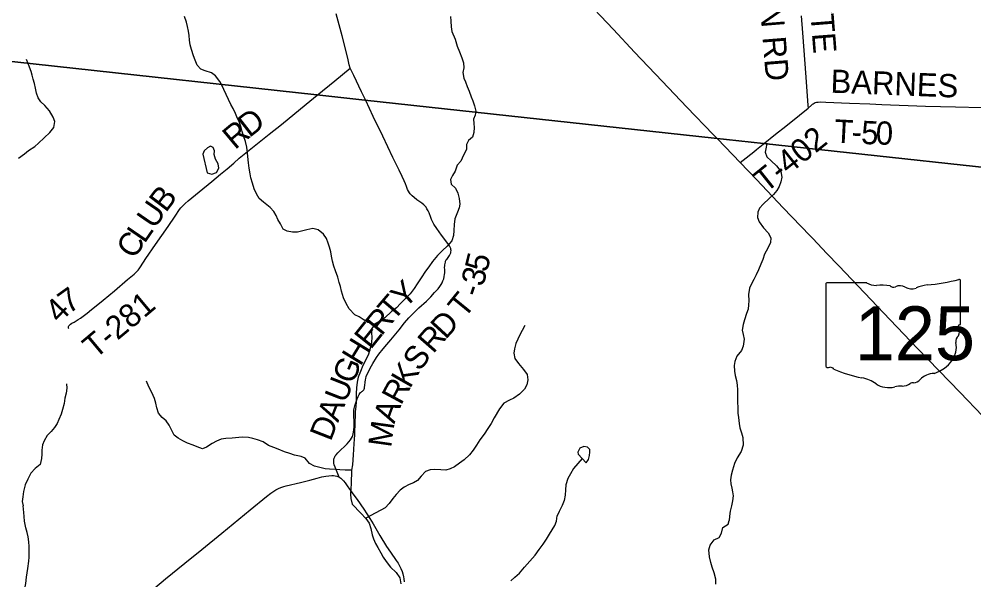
# Model space of a CAD drawing. Extents: x 1451455 to 1749751, y 218250 to 574981.
# Drawn here: x 1547410 to 1559745, y 321198 to 328437 of the extents above; entities that cross this region are included whole.
import ezdxf

# ---------------------------------------------------------------- set-up
doc = ezdxf.new("R2010")
doc.units = 0
for name, color, linetype in [('GM_X_County_Road', 7, 'Continuous'), ('GM_X_Minor_Lake', 7, 'Continuous'), ('GM_X_Minor_River', 7, 'Continuous'), ('GM_X_State_Location', 7, 'Continuous'), ('GM_X_State_Route', 7, 'Continuous'), ('GM_X_State_Shield', 7, 'Continuous'), ('GM_X_Township', 7, 'Continuous'), ('GM_X_Township_Road', 7, 'Continuous'), ('GM_X_Township_Road_Text', 7, 'Continuous')]:
    doc.layers.add(name, color=color, linetype=linetype)

msp = doc.modelspace()

# ---------------------------------------------------------------- linework, layer by layer
at = {"layer": 'GM_X_County_Road'}
for points in [[(1549163, 321095), (1549301, 321210), (1549551, 321413), (1549770, 321591), (1550029, 321803), (1550395, 322102), (1550608, 322276), (1550662, 322319), (1550699, 322345), (1550727, 322362), (1550760, 322378), (1550792, 322392), (1550829, 322404), (1550860, 322413), (1551046, 322455), (1551167, 322485), (1551261, 322512), (1551322, 322527), (1551372, 322538), (1551411, 322542), (1551450, 322544), (1551472, 322544), (1551493, 322542), (1551513, 322538), (1551535, 322530), (1551545, 322524)], [(1551545, 322524), (1551554, 322519), (1551566, 322511), (1551581, 322498), (1551601, 322477), (1551621, 322452), (1551650, 322412), (1551677, 322371), (1551703, 322333), (1551720, 322309), (1551776, 322237), (1551865, 322112), (1551942, 321991), (1551985, 321921), (1552069, 321773), (1552156, 321630), (1552207, 321557), (1552282, 321450), (1552305, 321415), (1552326, 321378), (1552343, 321343), (1552357, 321307), (1552368, 321274), (1552377, 321239), (1552382, 321213), (1552386, 321174)]]:
    msp.add_lwpolyline(points, dxfattribs=at)
at = {"layer": 'GM_X_Minor_Lake'}
for points in [[(1549838, 326451), (1549898, 326436), (1549962, 326457), (1549989, 326513), (1549982, 326571), (1549949, 326630), (1549930, 326690), (1549933, 326736), (1549917, 326779), (1549883, 326799), (1549845, 326776), (1549800, 326737), (1549782, 326695)], [(1549782, 326695), (1549838, 326451)], [(1554736, 322707), (1554766, 322753), (1554779, 322805), (1554782, 322847), (1554785, 322879), (1554753, 322910), (1554707, 322922), (1554655, 322899), (1554630, 322847), (1554633, 322821)], [(1554633, 322821), (1554736, 322707)]]:
    msp.add_lwpolyline(points, dxfattribs=at)
at = {"layer": 'GM_X_Minor_River'}
for points in [[(1552006, 324499), (1551917, 324522), (1551855, 324559), (1551802, 324592), (1551748, 324621), (1551675, 324696), (1551634, 324765), (1551601, 324838), (1551573, 324925), (1551560, 324985), (1551545, 325039), (1551526, 325108), (1551499, 325186), (1551478, 325247), (1551459, 325313), (1551446, 325375), (1551437, 325432), (1551418, 325494), (1551403, 325545), (1551379, 325603), (1551344, 325660), (1551275, 325719), (1551205, 325732), (1551127, 325719), (1551077, 325702), (1551006, 325685), (1550940, 325686), (1550875, 325699), (1550823, 325726), (1550786, 325793), (1550753, 325852), (1550730, 325902), (1550699, 325953), (1550655, 326007), (1550568, 326073), (1550513, 326120), (1550478, 326183), (1550447, 326245), (1550424, 326318), (1550403, 326390), (1550394, 326442), (1550381, 326515), (1550372, 326581), (1550366, 326663), (1550362, 326713), (1550350, 326782), (1550333, 326856), (1550310, 326929), (1550291, 326987), (1550280, 327037), (1550257, 327102), (1550231, 327156), (1550204, 327219), (1550175, 327284), (1550146, 327336), (1550115, 327401), (1550086, 327465), (1550055, 327528), (1550032, 327578), (1550003, 327631), (1549948, 327706), (1549897, 327743), (1549813, 327768), (1549759, 327791), (1549712, 327844), (1549685, 327907), (1549662, 327963), (1549635, 328044), (1549620, 328104), (1549613, 328164), (1549608, 328226), (1549599, 328283), (1549586, 328343), (1549571, 328399), (1549548, 328470)], [(1552983, 328471), (1552986, 328411), (1552993, 328336), (1553002, 328278), (1553042, 328177), (1553069, 328087), (1553098, 328016), (1553130, 327937), (1553151, 327873), (1553156, 327809), (1553143, 327749), (1553154, 327676), (1553175, 327626), (1553200, 327568), (1553226, 327507), (1553252, 327434), (1553270, 327382), (1553293, 327318), (1553311, 327249), (1553301, 327197), (1553280, 327145), (1553283, 327091), (1553288, 327039), (1553283, 326975), (1553266, 326915), (1553215, 326872), (1553190, 326820), (1553189, 326754), (1553150, 326679), (1553117, 326603), (1553068, 326550), (1553045, 326474), (1553008, 326420), (1552981, 326365), (1552992, 326306), (1553049, 326253), (1553076, 326191), (1553093, 326120), (1553102, 326050), (1553097, 326000), (1553074, 325944), (1553041, 325857), (1553032, 325785), (1553026, 325707), (1553021, 325645), (1553002, 325575), (1552941, 325508), (1552880, 325451), (1552815, 325384), (1552752, 325308), (1552703, 325239), (1552660, 325182), (1552602, 325096), (1552553, 325021), (1552512, 324960), (1552461, 324890), (1552335, 324768), (1552284, 324709), (1552221, 324664), (1552136, 324583), (1552079, 324542), (1552006, 324499), (1551967, 324445), (1551962, 324387), (1551965, 324325), (1551963, 324267)], [(1547403, 326643), (1547480, 326698), (1547533, 326739), (1547612, 326794), (1547662, 326837), (1547733, 326906), (1547807, 326973), (1547860, 327036), (1547873, 327114), (1547852, 327173), (1547803, 327254), (1547744, 327323), (1547691, 327368), (1547656, 327422), (1547635, 327483), (1547620, 327547), (1547609, 327605), (1547591, 327662), (1547580, 327712), (1547567, 327762), (1547546, 327815), (1547525, 327865), (1547505, 327916)], [(1557068, 326836), (1557063, 326786), (1557050, 326720), (1557069, 326661), (1557124, 326608), (1557195, 326543), (1557250, 326472), (1557265, 326396), (1557250, 326338), (1557231, 326278), (1557198, 326226), (1557157, 326175), (1557101, 326120), (1557023, 326049), (1556976, 325997), (1556954, 325944), (1556948, 325876), (1556972, 325819), (1557026, 325744), (1557085, 325679), (1557122, 325614), (1557115, 325554), (1557084, 325481), (1557041, 325401), (1557020, 325334), (1556993, 325272), (1556962, 325202), (1556933, 325137), (1556902, 325075), (1556873, 325021), (1556846, 324962), (1556834, 324880), (1556835, 324799), (1556834, 324747), (1556827, 324691), (1556808, 324638), (1556779, 324556), (1556762, 324496), (1556751, 324422), (1556766, 324366), (1556777, 324305), (1556764, 324214), (1556741, 324158), (1556684, 324087), (1556656, 324019), (1556646, 323965), (1556652, 323891), (1556662, 323838), (1556678, 323770), (1556687, 323710), (1556690, 323650), (1556691, 323573), (1556692, 323495), (1556693, 323419), (1556694, 323351), (1556703, 323293), (1556712, 323216), (1556721, 323160), (1556742, 323098), (1556759, 323037), (1556763, 322939), (1556736, 322855), (1556686, 322772), (1556653, 322702), (1556624, 322613), (1556609, 322549), (1556600, 322491), (1556603, 322437), (1556616, 322384), (1556627, 322334), (1556633, 322284), (1556627, 322220), (1556612, 322152), (1556597, 322086), (1556588, 322022), (1556581, 321964)], [(1553944, 324482), (1553909, 324418), (1553880, 324360), (1553851, 324305), (1553828, 324249), (1553809, 324179), (1553802, 324125), (1553813, 324057), (1553860, 323990), (1553926, 323913), (1553973, 323848), (1553984, 323782), (1553971, 323718), (1553938, 323660), (1553873, 323595), (1553802, 323542), (1553746, 323517), (1553673, 323478), (1553614, 323407), (1553548, 323288), (1553509, 323218), (1553466, 323151), (1553419, 323081), (1553363, 323008), (1553320, 322939), (1553277, 322873), (1553230, 322812), (1553161, 322749), (1553100, 322704), (1553036, 322657), (1552979, 322630), (1552923, 322614), (1552859, 322619), (1552781, 322625), (1552719, 322620), (1552660, 322595), (1552603, 322539), (1552556, 322480), (1552504, 322449), (1552451, 322428), (1552385, 322393), (1552332, 322355), (1552283, 322300), (1552240, 322249), (1552191, 322185), (1552140, 322130), (1551888, 321993)], [(1551963, 324267), (1551949, 324201), (1551922, 324111), (1551887, 324030), (1551852, 323964), (1551822, 323889), (1551789, 323815), (1551776, 323749), (1551769, 323677), (1551766, 323605), (1551764, 323499), (1551759, 323435), (1551752, 323373), (1551749, 323186), (1551744, 323132), (1551741, 323074), (1551738, 323012), (1551735, 322960), (1551730, 322880), (1551727, 322812), (1551722, 322746), (1551715, 322684), (1551702, 322614), (1551699, 322438), (1551696, 322378), (1551691, 322306), (1551696, 322247), (1551713, 322177), (1551825, 322061)], [(1548023, 323729), (1548026, 323675), (1548017, 323609), (1548002, 323543), (1547991, 323475), (1547969, 323397), (1547954, 323338), (1547925, 323270), (1547900, 323218), (1547866, 323167), (1547825, 323115), (1547774, 323060), (1547733, 322992), (1547714, 322941), (1547705, 322873), (1547702, 322821), (1547699, 322764), (1547680, 322689), (1547617, 322634), (1547560, 322574), (1547521, 322499), (1547489, 322425), (1547466, 322341), (1547457, 322271), (1547450, 322211), (1547463, 322155)], [(1551702, 322614), (1551622, 322613), (1551552, 322620), (1551496, 322621), (1551422, 322627), (1551364, 322633), (1551294, 322649), (1551224, 322666), (1551163, 322701), (1551106, 322768), (1551054, 322789), (1550966, 322810), (1550907, 322829), (1550839, 322852), (1550757, 322886), (1550700, 322909), (1550630, 322934), (1550565, 322979), (1550489, 323008), (1550429, 323025), (1550372, 323038), (1550302, 323041), (1550249, 323036), (1550163, 323028), (1550081, 323023), (1550021, 323014), (1549962, 322989), (1549904, 322958), (1549831, 322911), (1549779, 322891), (1549711, 322915), (1549659, 322935), (1549586, 322963), (1549526, 322994), (1549465, 323027), (1549413, 323068), (1549382, 323126), (1549347, 323195), (1549308, 323252), (1549257, 323293), (1549212, 323349), (1549191, 323418), (1549176, 323480), (1549157, 323541), (1549124, 323617), (1549087, 323688), (1549056, 323763)], [(1554686, 322763), (1554572, 322634), (1554533, 322566), (1554500, 322507), (1554473, 322425), (1554470, 322359), (1554463, 322291), (1554450, 322221), (1554425, 322157), (1554385, 322082), (1554360, 322026)], [(1547398, 320846), (1547432, 320916), (1547459, 321004), (1547486, 321087), (1547497, 321153), (1547507, 321233), (1547512, 321289), (1547521, 321347), (1547534, 321441), (1547539, 321493), (1547540, 321545), (1547539, 321627), (1547534, 321691), (1547525, 321754), (1547516, 321808), (1547499, 321870), (1547481, 321957), (1547474, 322015), (1547469, 322067), (1547463, 322155)], [(1551825, 322061), (1551890, 321990), (1551933, 321932), (1551952, 321863), (1551972, 321781), (1551988, 321726), (1552015, 321668), (1552044, 321617), (1552082, 321545), (1552114, 321490), (1552151, 321434), (1552209, 321362), (1552280, 321293), (1552329, 321226), (1552340, 321148)], [(1553761, 321186), (1553816, 321233), (1553873, 321285), (1553938, 321362), (1554009, 321441), (1554078, 321516), (1554128, 321591), (1554179, 321658), (1554222, 321722), (1554263, 321789), (1554298, 321843), (1554329, 321900), (1554352, 321954), (1554360, 322026)], [(1556409, 321143), (1556412, 321207), (1556391, 321287), (1556364, 321364), (1556345, 321424), (1556327, 321497), (1556320, 321585), (1556337, 321647), (1556390, 321716), (1556453, 321747), (1556483, 321801), (1556503, 321876), (1556571, 321919), (1556581, 321964)]]:
    msp.add_lwpolyline(points, dxfattribs=at)
at = {"layer": 'GM_X_State_Route'}
for points in [[(1554669, 328747), (1555090, 328301), (1555362, 328012), (1555719, 327636), (1556038, 327301), (1556376, 326948), (1556432, 326890), (1556724, 326585), (1556935, 326365), (1557281, 326002), (1557625, 325642)], [(1557625, 325642), (1557662, 325603), (1557843, 325413), (1557998, 325253), (1558661, 324553), (1559015, 324187)], [(1559015, 324187), (1559567, 323616), (1559857, 323317), (1560082, 323088)]]:
    msp.add_lwpolyline(points, dxfattribs=at)
at = {"layer": 'GM_X_State_Shield'}
for p, q in [((1558360, 325034), (1557850, 325034)), ((1559573, 324507), (1559573, 325060)), ((1557833, 325015), (1557833, 323959)), ((1559573, 324507), (1559573, 324507))]:
    msp.add_line(p, q, dxfattribs=at)
for centre, major_axis, start_param, end_param in [((1557853, 325018), (20.2, 0), 1.712693, 3.28349), ((1558481, 325156), (196, 0), 4.042523, 4.731795), ((1558953, 326474), (1845, 0), 4.814394, 5.042369), ((1559554, 325062), (19.4, 0), 6.141152, 7.989035), ((1558546, 324440), (702, 0), 1.404758, 1.657858), ((1558705, 325023), (56.4, 0), 3.836095, 5.185415), ((1558788, 324901), (117, 0), 0.950623, 2.079405), ((1558939, 325068), (141, 0), 4.081561, 5.145723), ((1559188, 324711), (371, 0), 1.699011, 2.107814), ((1559568, 324466), (30, 0), 1.883978, 3.671073), ((1559378, 324397), (180, 0), 5.934695, 6.695948), ((1559552, 324505), (20.7, 0), 5.05454, 6.418171), ((1559642, 324276), (131, 0), 2.387724, 3.262537), ((1559056, 324205), (462, 0), 5.101752, 6.440018), ((1557853, 323956), (20.3, 0), 3.00124, 4.508301), ((1557856, 324064), (155, 0), 4.665946, 4.897461), ((1557888, 323898), (56, 0), 0.519207, 1.627899), ((1558594, 324847), (1333, 0), 4.195997, 4.488961), ((1558197, 323484), (417, 0), 0.823519, 1.323587), ((1559251, 323662), (253, 0), 1.647645, 2.488434), ((1558648, 323892), (265, 0), 4.026481, 4.996735), ((1558801, 323527), (217, 0), 1.495662, 1.94098), ((1558820, 323813), (141, 0), 4.691044, 5.507374), ((1558948, 323711), (39.7, 0), 1.147584, 2.315152), ((1558931, 323856), (149, 0), 4.937069, 5.64225)]:
    msp.add_ellipse(centre, major_axis=major_axis, ratio=0.8, start_param=start_param, end_param=end_param, dxfattribs=at)
at = {"layer": 'GM_X_Township'}
for points in [[(1563519, 329001), (1563355, 328353), (1563521, 328135), (1563800, 327944), (1564061, 327870), (1564544, 327884), (1564851, 327745), (1565264, 327621), (1565559, 327212), (1565722, 326761), (1565674, 326366), (1565439, 325922), (1565430, 325917), (1561235, 326376), (1557027, 326832), (1556391, 326901), (1551877, 327393), (1551255, 327461), (1544473, 328202)], [(1544473, 328202), (1551255, 327461), (1551877, 327393), (1556391, 326901), (1557027, 326832), (1561235, 326376)]]:
    msp.add_lwpolyline(points, dxfattribs=at)
at = {"layer": 'GM_X_Township_Road'}
for points in [[(1551689, 327805), (1551676, 327846), (1551655, 327932), (1551582, 328222), (1551507, 328504)], [(1557515, 328481), (1557532, 328258), (1557574, 327686), (1557600, 327322), (1557603, 327288)], [(1551260, 327454), (1551487, 327639), (1551689, 327805)], [(1551889, 327386), (1551835, 327498), (1551735, 327708), (1551689, 327805)], [(1548052, 324437), (1548050, 324447), (1548048, 324456), (1548048, 324467), (1548051, 324476), (1548055, 324483), (1548064, 324491), (1548075, 324499), (1548091, 324510), (1548121, 324527), (1548175, 324559), (1548203, 324576), (1548237, 324601), (1548288, 324642), (1548344, 324687), (1548405, 324737), (1548494, 324809), (1548641, 324931), (1548811, 325074), (1548897, 325146), (1548930, 325177), (1548948, 325196), (1548963, 325214), (1548980, 325238), (1549048, 325346), (1549170, 325529), (1549336, 325761), (1549425, 325895), (1549483, 325978), (1549501, 326001), (1549528, 326030), (1549556, 326057), (1549596, 326091), (1549737, 326206), (1549900, 326341), (1550011, 326434), (1550097, 326504), (1550185, 326578), (1550255, 326640), (1550553, 326884), (1550642, 326951), (1550798, 327077), (1551120, 327341), (1551260, 327454)], [(1551545, 322524), (1551491, 322655), (1551482, 322682), (1551477, 322705), (1551474, 322725), (1551474, 322741), (1551475, 322756), (1551479, 322770), (1551487, 322785), (1551494, 322799), (1551506, 322812), (1551527, 322836), (1551571, 322879), (1551610, 322915), (1551646, 322953), (1551670, 322979), (1551693, 323008), (1551704, 323028), (1551716, 323049), (1551721, 323062), (1551727, 323085), (1551731, 323104), (1551736, 323134), (1551739, 323173), (1551740, 323206), (1551738, 323238), (1551733, 323320), (1551733, 323353), (1551735, 323387), (1551739, 323410), (1551742, 323427), (1551746, 323443), (1551750, 323456), (1551763, 323497), (1551776, 323534), (1551790, 323564), (1551803, 323591), (1551812, 323605), (1551820, 323615), (1551827, 323622), (1551837, 323628), (1551846, 323635), (1551856, 323644), (1551863, 323652), (1551868, 323660), (1551871, 323672), (1551873, 323685), (1551875, 323708), (1551880, 323750), (1551884, 323779), (1551888, 323798), (1551895, 323824), (1551903, 323845), (1551918, 323877), (1551947, 323933), (1551981, 323993), (1552026, 324068), (1552056, 324110), (1552112, 324179), (1552161, 324236), (1552214, 324298), (1552320, 324428), (1552390, 324515), (1552445, 324580), (1552483, 324620), (1552527, 324664), (1552576, 324708), (1552674, 324797), (1552728, 324852), (1552777, 324906), (1552823, 324957), (1552845, 324985), (1552862, 325010), (1552874, 325033), (1552885, 325057), (1552895, 325084), (1552902, 325113), (1552907, 325139), (1552908, 325163), (1552908, 325205), (1552907, 325230), (1552908, 325251), (1552909, 325264), (1552912, 325282), (1552917, 325301), (1552920, 325311), (1552924, 325320), (1552929, 325328), (1552934, 325336), (1552951, 325360), (1552969, 325384), (1552979, 325401), (1552986, 325419), (1552989, 325435), (1552990, 325452), (1552989, 325465), (1552986, 325478), (1552980, 325494), (1552970, 325510), (1552935, 325557), (1552865, 325650), (1552805, 325734), (1552768, 325792), (1552751, 325824), (1552739, 325850), (1552728, 325878), (1552706, 325936), (1552694, 325963), (1552679, 325990), (1552668, 326008), (1552653, 326026), (1552640, 326040), (1552614, 326061), (1552549, 326105), (1552513, 326133), (1552488, 326155), (1552470, 326173), (1552461, 326183), (1552453, 326194), (1552439, 326216), (1552429, 326238), (1552415, 326277), (1552403, 326311), (1552386, 326350), (1552360, 326406), (1552319, 326489), (1552240, 326651), (1552108, 326926), (1551986, 327181), (1551889, 327386)], [(1557603, 327288), (1557646, 327325), (1557660, 327338), (1557670, 327345), (1557681, 327353), (1557696, 327360), (1557712, 327364), (1557731, 327367), (1557764, 327368), (1557830, 327367), (1558138, 327354), (1558400, 327343)], [(1557022, 326823), (1557180, 326950), (1557313, 327056), (1557491, 327196), (1557603, 327288)], [(1558400, 327343), (1558554, 327337), (1559118, 327315), (1559508, 327305), (1559849, 327296), (1560078, 327288), (1560396, 327274), (1560654, 327258), (1561044, 327230), (1561304, 327211)], [(1556902, 326726), (1556937, 326754), (1557022, 326823)], [(1556724, 326585), (1556762, 326615), (1556902, 326726)]]:
    msp.add_lwpolyline(points, dxfattribs=at)

# ---------------------------------------------------------------- texts
at = {"layer": 'GM_X_State_Location'}
for s in ['s', 'r']:
    msp.add_text(s, height=1, dxfattribs=at).set_placement((1558683, 324417))
msp.add_text('125', height=1, rotation=0, dxfattribs=at).set_placement((1558330, 324344))
at = {"layer": 'GM_X_State_Shield'}
msp.add_text('125', height=696.1, dxfattribs=at).set_placement((1558206, 324033))
at = {"layer": 'GM_X_Township_Road_Text'}
for s, rotation, p in [('STATION RD', 274.5998, (1556865, 330049)), ('GILLETTE', 274.5102, (1557524, 329874)), ('BARNES', 357.7581, (1557889, 327488)), ('D', 37.9034, (1550384, 326899)), ('T', 357.0373, (1557934, 326845)), ('5', 357.3505, (1558283, 326827)), ('0', 358.5255, (1558474, 326819)), ('R', 40.0262, (1550198, 326743)), ('T-402', 38.7035, (1557055, 326185)), ('-', 357.0954, (1558158, 326834)), ('B', 52.6676, (1549305, 325930)), ('U', 55.4577, (1549157, 325715)), ('C', 56.659, (1548896, 325326)), ('L', 55.5397, (1549030, 325530)), ('5', 76.1178, (1553454, 325158)), ('3', 74.9562, (1553404, 324973)), ('Y', 43.4054, (1552386, 324690)), ('7', 35.662, (1548050, 324623)), ('T', 49.4226, (1552246, 324526)), ('T', 50.8757, (1553160, 324561)), ('-', 70.6676, (1553356, 324833)), ('4', 46.0525, (1547932, 324499)), ('T-281', 39.9461, (1548391, 324041)), ('R', 50.6682, (1552091, 324337)), ('E', 51.3174, (1551951, 324162)), ('D', 47.4581, (1552919, 324293)), ('R', 48.8418, (1552758, 324109)), ('H', 58.5752, (1551819, 323945)), ('S', 53.9293, (1552586, 323878)), ('G', 67.3151, (1551723, 323712)), ('K', 60.1505, (1552459, 323657)), ('U', 68.6078, (1551627, 323468)), ('R', 61.7495, (1552344, 323442)), ('A', 68.622, (1551531, 323222)), ('A', 69.6622, (1552257, 323204)), ('D', 68.6234, (1551435, 322976)), ('M', 81.9083, (1552215, 322898))]:
    msp.add_text(s, height=300, rotation=rotation, dxfattribs=at).set_placement(p)

doc.saveas('drawing.dxf')
